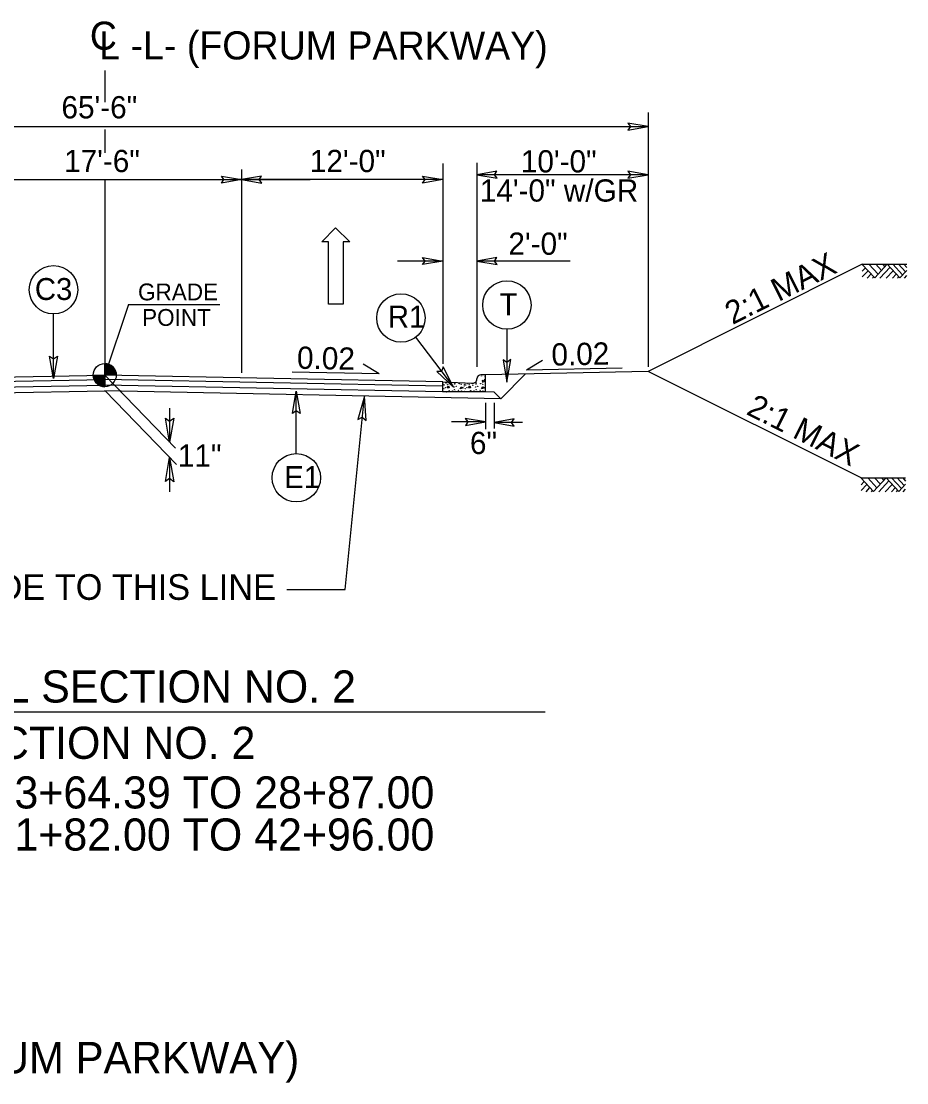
# Model space of a CAD drawing. Extents: x 1904401 to 1905163, y 193929 to 194736.
# Drawn here: x 1904906.8 to 1904958.5, y 194556.6 to 194618.6 of the extents above; entities that cross this region are included whole.
import ezdxf

# ---------------------------------------------------------------- set-up
doc = ezdxf.new("R2010")
doc.units = 0
for name, color, linetype in [('Default', 7, 'Continuous'), ('Old_Level_1', 7, 'Continuous'), ('Old_Level_11', 7, 'Continuous'), ('Old_Level_20', 7, 'Continuous'), ('Old_Level_3', 7, 'Continuous'), ('Prop Dimension Text', 7, 'Continuous'), ('Prop Lane Arrow CELL', 7, 'Continuous'), ('Typical Arrow Superelevation CELL', 7, 'Continuous'), ('Typical Berm CELL', 7, 'Continuous'), ('Typical Curb CELL', 7, 'Continuous'), ('Typical Hinge Slope Arterial CELL', 7, 'Continuous'), ('Typical Pavement Slope CELL', 7, 'Continuous'), ('Typical Terminator CELL', 7, 'Continuous'), ('Typical Text Centerline CELL', 7, 'Continuous')]:
    doc.layers.add(name, color=color, linetype=linetype)

# ---------------------------------------------------------------- blocks, each defined once
blk = doc.blocks.new('TERMINATOR')
at = {"layer": 'Typical Terminator CELL'}
blk.add_lwpolyline([(-0.469, 0.081), (0, 0), (-0.471, -0.083), (-0.411, 0)], close=True, dxfattribs=at)

msp = doc.modelspace()

# ---------------------------------------------------------------- linework, layer by layer
at = {"layer": 'Default'}
for p, q in [((1904931.41, 194610.268), (1904931.41, 194598.57)), ((1904919.66, 194609.923), (1904919.66, 194598.051))]:
    msp.add_line(p, q, dxfattribs=at)
at = {"layer": 'Old_Level_1'}
for p, q in [((1904879.91, 194612.433), (1904943.41, 194612.433)), ((1904903.66, 194609.34), (1904919.66, 194609.34)), ((1904931.41, 194609.34), (1904919.41, 194609.34)), ((1904943.41, 194609.62), (1904933.41, 194609.62)), ((1904931.41, 194604.574), (1904928.769, 194604.574)), ((1904938.856, 194604.574), (1904933.41, 194604.574)), ((1904955.93, 194604.38), (1904956.654, 194603.601)), ((1904956.321, 194604.388), (1904956.854, 194603.815)), ((1904956.654, 194603.601), (1904957.385, 194604.387)), ((1904956.719, 194604.388), (1904957.052, 194604.029)), ((1904957.121, 194604.388), (1904957.254, 194604.245)), ((1904957.385, 194604.387), (1904958.126, 194603.591)), ((1904957.707, 194604.388), (1904958.287, 194603.765)), ((1904958.04, 194604.388), (1904958.454, 194603.944)), ((1904958.36, 194604.388), (1904958.53, 194604.205)), ((1904955.93, 194603.979), (1904956.116, 194604.179)), ((1904955.93, 194603.646), (1904956.272, 194604.012)), ((1904956.218, 194603.583), (1904956.445, 194603.826)), ((1904956.964, 194603.583), (1904957.55, 194604.211)), ((1904957.334, 194603.583), (1904957.734, 194604.012)), ((1904957.7, 194603.583), (1904957.917, 194603.816)), ((1904958.126, 194603.591), (1904958.53, 194604.026)), ((1904956.529, 194603.583), (1904956.6, 194603.659)), ((1904957.995, 194603.583), (1904958.064, 194603.657)), ((1904958.396, 194603.583), (1904958.53, 194603.726)), ((1904911.66, 194597.909), (1904911.66, 194598.584)), ((1904910.985, 194597.909), (1904911.66, 194597.909)), ((1904911.658, 194597.234), (1904911.66, 194597.909)), ((1904911.66, 194597.909), (1904911.658, 194597.234)), ((1904912.335, 194597.909), (1904911.66, 194597.909)), ((1904911.66, 194597.909), (1904915.793, 194593.639)), ((1904911.678, 194596.992), (1904915.85, 194592.682)), ((1904915.454, 194595.989), (1904915.454, 194593.989)), ((1904915.449, 194593.096), (1904915.449, 194591.096)), ((1904955.862, 194591.894), (1904956.586, 194591.115)), ((1904955.862, 194591.493), (1904956.048, 194591.693)), ((1904955.862, 194591.16), (1904956.205, 194591.526)), ((1904956.151, 194591.097), (1904956.377, 194591.34)), ((1904956.254, 194591.902), (1904956.786, 194591.329)), ((1904956.586, 194591.115), (1904957.318, 194591.901)), ((1904956.652, 194591.902), (1904956.985, 194591.543)), ((1904956.896, 194591.097), (1904957.483, 194591.725)), ((1904957.053, 194591.902), (1904957.187, 194591.759)), ((1904957.267, 194591.097), (1904957.667, 194591.526)), ((1904957.318, 194591.901), (1904958.058, 194591.105)), ((1904957.639, 194591.902), (1904958.22, 194591.279)), ((1904957.972, 194591.902), (1904958.387, 194591.458)), ((1904958.058, 194591.105), (1904958.462, 194591.54)), ((1904958.293, 194591.902), (1904958.463, 194591.719)), ((1904956.461, 194591.097), (1904956.533, 194591.173)), ((1904957.633, 194591.097), (1904957.85, 194591.33)), ((1904957.927, 194591.097), (1904957.997, 194591.171)), ((1904958.328, 194591.097), (1904958.463, 194591.24)), ((1904884.997, 194578.236), (1904937.39, 194578.236))]:
    msp.add_line(p, q, dxfattribs=at)
for points in [[(1904955.93, 194604.388), (1904958.53, 194604.388)], [(1904911.666, 194598.584), (1904911.666, 194598.584), (1904911.666, 194597.909)], [(1904911.679, 194598.584), (1904911.679, 194597.909)], [(1904911.693, 194598.582), (1904911.693, 194597.909)], [(1904911.706, 194598.582), (1904911.706, 194597.909)], [(1904911.72, 194598.581), (1904911.72, 194597.909)], [(1904911.733, 194598.579), (1904911.733, 194597.909)], [(1904911.747, 194598.578), (1904911.747, 194597.909)], [(1904911.76, 194598.576), (1904911.76, 194597.909)], [(1904911.774, 194598.575), (1904911.774, 194597.909)], [(1904911.787, 194598.572), (1904911.787, 194597.909)], [(1904911.801, 194598.569), (1904911.801, 194597.909)], [(1904911.814, 194598.566), (1904911.814, 194597.909)], [(1904911.828, 194598.563), (1904911.828, 194597.909)], [(1904911.841, 194598.558), (1904911.841, 194597.909)], [(1904911.855, 194598.555), (1904911.855, 194597.909)], [(1904911.868, 194598.551), (1904911.868, 194597.909)], [(1904911.882, 194598.546), (1904911.882, 194597.909)], [(1904911.895, 194598.542), (1904911.895, 194597.909)], [(1904911.909, 194598.536), (1904911.909, 194597.909)], [(1904911.922, 194598.53), (1904911.922, 194597.909)], [(1904911.936, 194598.524), (1904911.936, 194597.909)], [(1904911.949, 194598.518), (1904911.949, 194597.909)], [(1904911.963, 194598.512), (1904911.963, 194597.909)], [(1904911.976, 194598.504), (1904911.976, 194597.909)], [(1904911.99, 194598.497), (1904911.99, 194597.909)], [(1904912.003, 194598.489), (1904912.003, 194597.909)], [(1904912.017, 194598.482), (1904912.017, 194597.909)], [(1904912.03, 194598.473), (1904912.03, 194597.909)], [(1904912.044, 194598.464), (1904912.044, 194597.909)], [(1904912.057, 194598.453), (1904912.057, 194597.909)], [(1904912.071, 194598.444), (1904912.071, 194597.909)], [(1904912.084, 194598.434), (1904912.084, 194597.909)], [(1904912.098, 194598.422), (1904912.098, 194597.909)], [(1904912.111, 194598.41), (1904912.111, 194597.909)], [(1904912.125, 194598.398), (1904912.125, 194597.909)], [(1904912.138, 194598.384), (1904912.138, 194597.909)], [(1904912.152, 194598.371), (1904912.152, 194597.909)], [(1904912.165, 194598.356), (1904912.165, 194597.909)], [(1904912.179, 194598.339), (1904912.179, 194597.909)], [(1904912.192, 194598.323), (1904912.192, 194597.909)], [(1904912.206, 194598.305), (1904912.206, 194597.909)], [(1904912.219, 194598.285), (1904912.219, 194597.909)], [(1904912.233, 194598.264), (1904912.233, 194597.909)], [(1904912.246, 194598.242), (1904912.246, 194597.909)], [(1904912.26, 194598.218), (1904912.26, 194597.909)], [(1904912.273, 194598.189), (1904912.273, 194597.909)], [(1904912.287, 194598.158), (1904912.287, 194597.909)], [(1904910.988, 194597.909), (1904910.988, 194597.835)], [(1904911.001, 194597.909), (1904911.001, 194597.756)], [(1904911.015, 194597.909), (1904911.015, 194597.708)], [(1904911.028, 194597.909), (1904911.028, 194597.667)], [(1904911.042, 194597.909), (1904911.042, 194597.636)], [(1904911.055, 194597.909), (1904911.055, 194597.607)], [(1904911.069, 194597.909), (1904911.069, 194597.582)], [(1904911.082, 194597.909), (1904911.082, 194597.558)], [(1904911.096, 194597.909), (1904911.096, 194597.537)], [(1904911.109, 194597.909), (1904911.109, 194597.517)], [(1904911.123, 194597.909), (1904911.123, 194597.499)], [(1904911.136, 194597.909), (1904911.136, 194597.483)], [(1904911.15, 194597.909), (1904911.15, 194597.466)], [(1904911.163, 194597.909), (1904911.163, 194597.451)], [(1904911.177, 194597.909), (1904911.177, 194597.436)], [(1904911.19, 194597.909), (1904911.19, 194597.423)], [(1904911.204, 194597.909), (1904911.204, 194597.411)], [(1904911.217, 194597.909), (1904911.217, 194597.399)], [(1904911.231, 194597.909), (1904911.231, 194597.387)], [(1904911.244, 194597.909), (1904911.244, 194597.376)], [(1904911.258, 194597.909), (1904911.258, 194597.366)], [(1904911.271, 194597.909), (1904911.271, 194597.357)], [(1904911.285, 194597.909), (1904911.285, 194597.348)], [(1904911.298, 194597.909), (1904911.298, 194597.339)], [(1904911.312, 194597.909), (1904911.312, 194597.33)], [(1904911.325, 194597.909), (1904911.325, 194597.322)], [(1904911.339, 194597.909), (1904911.339, 194597.315)], [(1904911.352, 194597.909), (1904911.352, 194597.307)], [(1904911.366, 194597.909), (1904911.366, 194597.301)], [(1904911.379, 194597.909), (1904911.379, 194597.295)], [(1904911.393, 194597.909), (1904911.393, 194597.289)], [(1904911.406, 194597.909), (1904911.406, 194597.283)], [(1904911.42, 194597.909), (1904911.42, 194597.277)], [(1904911.433, 194597.909), (1904911.433, 194597.273)], [(1904911.447, 194597.909), (1904911.447, 194597.268)], [(1904911.46, 194597.909), (1904911.46, 194597.264)], [(1904911.474, 194597.909), (1904911.474, 194597.261)], [(1904911.487, 194597.909), (1904911.487, 194597.256)], [(1904911.501, 194597.909), (1904911.501, 194597.253)], [(1904911.514, 194597.909), (1904911.514, 194597.25)], [(1904911.528, 194597.909), (1904911.528, 194597.247)], [(1904911.541, 194597.909), (1904911.541, 194597.244)], [(1904911.555, 194597.909), (1904911.555, 194597.243)], [(1904911.568, 194597.909), (1904911.568, 194597.24)], [(1904911.582, 194597.909), (1904911.582, 194597.238)], [(1904911.595, 194597.909), (1904911.595, 194597.237)], [(1904911.609, 194597.909), (1904911.609, 194597.235)], [(1904911.622, 194597.909), (1904911.622, 194597.235)], [(1904911.636, 194597.909), (1904911.636, 194597.234)], [(1904911.649, 194597.909), (1904911.649, 194597.234), (1904911.649, 194597.234)], [(1904912.3, 194598.12), (1904912.3, 194597.909)], [(1904912.314, 194598.074), (1904912.314, 194597.909)], [(1904912.327, 194598.005), (1904912.327, 194597.909)], [(1904955.862, 194591.902), (1904958.462, 194591.902)]]:
    msp.add_lwpolyline(points, dxfattribs=at)
msp.add_circle((1904911.659, 194597.909), 0.675, dxfattribs=at)
for start, end in [(359.99048, 89.99048), (179.99048, 269.99048)]:
    msp.add_arc((1904911.659, 194597.909), 0.675, start, end, dxfattribs=at)
at = {"layer": 'Old_Level_11'}
for p, q in [((1904908.667, 194597.706), (1904908.667, 194601.485)), ((1904929.828, 194600.123), (1904932.04, 194597.214)), ((1904935.164, 194600.592), (1904935.164, 194597.502)), ((1904922.857, 194593.327), (1904922.857, 194596.982))]:
    msp.add_line(p, q, dxfattribs=at)
for points in [[(1904908.892, 194599.015), (1904908.667, 194597.706), (1904908.434, 194599.022), (1904908.667, 194598.855)], [(1904934.939, 194598.811), (1904935.164, 194597.502), (1904935.397, 194598.818), (1904935.164, 194598.651)], [(1904931.068, 194598.12), (1904932.04, 194597.214), (1904931.429, 194598.403), (1904931.345, 194598.129)], [(1904922.632, 194595.672), (1904922.857, 194596.982), (1904923.09, 194595.665), (1904922.857, 194595.833)]]:
    msp.add_lwpolyline(points, close=True, dxfattribs=at)
for centre in [(1904908.667, 194602.899), (1904935.164, 194602.006), (1904928.972, 194601.249), (1904922.858, 194591.913)]:
    msp.add_circle(centre, 1.414, dxfattribs=at)
at = {"layer": 'Old_Level_3'}
for q in [(1904911.66, 194597.909), (1904918.393, 194602.042)]:
    msp.add_line((1904913.047, 194602.042), q, dxfattribs=at)
at = {"layer": 'Prop Dimension Text'}
for p, q in [((1904943.41, 194613.26), (1904943.41, 194598.394)), ((1904933.41, 194610.313), (1904933.41, 194598.394)), ((1904930.66, 194609.34), (1904919.66, 194609.34)), ((1904919.66, 194609.34), (1904923.66, 194609.34))]:
    msp.add_line(p, q, dxfattribs=at)
at = {"layer": 'Prop Lane Arrow CELL'}
for p, q in [((1904924.346, 194605.693), (1904925.15, 194606.51)), ((1904925.15, 194606.51), (1904925.98, 194605.693)), ((1904924.735, 194605.693), (1904924.346, 194605.693)), ((1904924.735, 194602.062), (1904924.735, 194605.693)), ((1904925.98, 194605.693), (1904925.591, 194605.693)), ((1904925.591, 194605.693), (1904925.591, 194602.062)), ((1904925.591, 194602.062), (1904924.735, 194602.062)), ((1904925.704, 194585.387), (1904926.847, 194596.688)), ((1904933.909, 194596.29), (1904933.909, 194594.751)), ((1904934.409, 194596.289), (1904934.409, 194594.791)), ((1904933.909, 194595.173), (1904931.919, 194595.173)), ((1904936.081, 194595.145), (1904934.409, 194595.145)), ((1904922.305, 194585.387), (1904925.704, 194585.387))]:
    msp.add_line(p, q, dxfattribs=at)
at = {"layer": 'Typical Arrow Superelevation CELL'}
for p, q in [((1904936.303, 194598.225), (1904937.243, 194598.793)), ((1904927.695, 194597.978), (1904926.755, 194598.546)), ((1904936.303, 194598.225), (1904941.896, 194598.337)), ((1904927.695, 194597.978), (1904922.624, 194598.08))]:
    msp.add_line(p, q, dxfattribs=at)
at = {"layer": 'Typical Berm CELL'}
msp.add_line((1904943.41, 194598.128), (1904933.909, 194597.93), dxfattribs=at)
at = {"layer": 'Typical Curb CELL'}
for p, q in [((1904933.409, 194597.68), (1904933.409, 194597.691)), ((1904933.909, 194597.93), (1904933.649, 194597.93)), ((1904933.719, 194597.597), (1904933.735, 194597.506)), ((1904933.873, 194597.552), (1904933.719, 194597.597)), ((1904933.735, 194597.506), (1904933.873, 194597.552)), ((1904933.909, 194596.931), (1904933.909, 194597.93)), ((1904931.41, 194596.931), (1904931.41, 194597.514)), ((1904931.41, 194597.514), (1904933.16, 194597.441)), ((1904933.909, 194596.931), (1904931.41, 194596.931)), ((1904931.67, 194597.17), (1904931.757, 194597.29)), ((1904931.791, 194597.176), (1904931.67, 194597.17)), ((1904931.757, 194597.29), (1904931.791, 194597.176)), ((1904932.436, 194597.119), (1904932.498, 194597.234)), ((1904932.601, 194597.159), (1904932.436, 194597.119)), ((1904932.498, 194597.234), (1904932.601, 194597.159)), ((1904932.92, 194597.17), (1904933.005, 194597.29)), ((1904933.04, 194597.176), (1904932.92, 194597.17)), ((1904933.005, 194597.29), (1904933.04, 194597.176)), ((1904933.684, 194597.119), (1904933.747, 194597.234)), ((1904933.85, 194597.159), (1904933.684, 194597.119)), ((1904933.747, 194597.234), (1904933.85, 194597.159))]:
    msp.add_line(p, q, dxfattribs=at)
for centre in [(1904933.679, 194597.855), (1904933.845, 194597.638), (1904933.896, 194597.82), (1904931.421, 194596.959), (1904931.426, 194597.268), (1904931.443, 194597.365), (1904931.483, 194597.125), (1904931.499, 194597.33), (1904931.579, 194597.17), (1904931.608, 194597.455), (1904931.631, 194596.937), (1904931.705, 194597.37), (1904931.751, 194597.472), (1904931.791, 194597.005), (1904931.899, 194597.409), (1904931.928, 194597.308), (1904931.996, 194596.982), (1904932.076, 194597.222), (1904932.105, 194597.393), (1904932.11, 194597.068), (1904932.122, 194597.444), (1904932.167, 194596.954), (1904932.202, 194597.25), (1904932.344, 194597.016), (1904932.378, 194597.415), (1904932.498, 194597.365), (1904932.515, 194596.976), (1904932.67, 194596.959), (1904932.675, 194597.268), (1904932.692, 194597.365), (1904932.732, 194597.125), (1904932.748, 194597.33), (1904932.829, 194597.17), (1904932.857, 194597.424), (1904932.88, 194596.937), (1904932.954, 194597.37), (1904933.04, 194597.005), (1904933.148, 194597.409), (1904933.177, 194597.308), (1904933.245, 194596.982), (1904933.325, 194597.222), (1904933.354, 194597.393), (1904933.359, 194597.068), (1904933.371, 194597.444), (1904933.416, 194596.954), (1904933.451, 194597.25), (1904933.593, 194597.016), (1904933.628, 194597.415), (1904933.748, 194597.365), (1904933.765, 194596.976)]:
    msp.add_circle(centre, 0.00802, dxfattribs=at)
for centre, start, end in [((1904933.17, 194597.68), 267.61554, 0), ((1904933.649, 194597.691), 90, 180)]:
    msp.add_arc(centre, 0.24, start, end, dxfattribs=at)
at = {"layer": 'Typical Hinge Slope Arterial CELL'}
for p in [(1904955.93, 194604.388), (1904955.862, 194591.902)]:
    msp.add_line(p, (1904943.41, 194598.128), dxfattribs=at)
at = {"layer": 'Typical Pavement Slope CELL'}
for p, q in [((1904891.91, 194597.514), (1904911.66, 194597.909)), ((1904891.915, 194597.264), (1904911.665, 194597.659)), ((1904931.405, 194597.264), (1904911.655, 194597.659)), ((1904931.41, 194597.514), (1904911.66, 194597.909)), ((1904934.799, 194596.531), (1904936.247, 194597.979)), ((1904888.519, 194596.529), (1904911.678, 194596.992)), ((1904891.921, 194596.931), (1904911.671, 194597.326)), ((1904934.801, 194596.529), (1904911.641, 194596.992)), ((1904931.398, 194596.931), (1904911.648, 194597.326)), ((1904934.409, 194596.921), (1904933.909, 194596.931)), ((1904934.801, 194596.529), (1904934.409, 194596.921))]:
    msp.add_line(p, q, dxfattribs=at)
at = {"layer": 'Typical Terminator CELL'}
for points in [[(1904942.238, 194612.231), (1904943.41, 194612.433), (1904942.232, 194612.641), (1904942.381, 194612.433)], [(1904918.488, 194609.542), (1904919.66, 194609.34), (1904918.482, 194609.132), (1904918.631, 194609.34)], [(1904920.831, 194609.542), (1904919.66, 194609.34), (1904920.838, 194609.132), (1904920.688, 194609.34)], [(1904930.238, 194609.542), (1904931.41, 194609.34), (1904930.232, 194609.132), (1904930.381, 194609.34)], [(1904934.581, 194609.822), (1904933.41, 194609.62), (1904934.588, 194609.412), (1904934.438, 194609.62)], [(1904942.238, 194609.418), (1904943.41, 194609.62), (1904942.232, 194609.828), (1904942.381, 194609.62)], [(1904930.238, 194604.776), (1904931.41, 194604.574), (1904930.232, 194604.366), (1904930.381, 194604.574)], [(1904934.581, 194604.776), (1904933.41, 194604.574), (1904934.588, 194604.366), (1904934.438, 194604.574)], [(1904926.934, 194595.264), (1904926.847, 194596.688), (1904926.444, 194595.31), (1904926.712, 194595.461)], [(1904932.738, 194594.971), (1904933.909, 194595.173), (1904932.731, 194595.381), (1904932.881, 194595.173)], [(1904935.581, 194595.347), (1904934.409, 194595.145), (1904935.587, 194594.937), (1904935.438, 194595.145)]]:
    msp.add_lwpolyline(points, close=True, dxfattribs=at)
at = {"layer": 'Typical Text Centerline CELL'}
for p, q in [((1904911.66, 194615.715), (1904911.66, 194613.867)), ((1904911.66, 194612.261), (1904911.66, 194610.892)), ((1904911.66, 194609.34), (1904911.66, 194597.979))]:
    msp.add_line(p, q, dxfattribs=at)

# ---------------------------------------------------------------- block references
at = {"layer": 'Old_Level_1', "xscale": 3, "yscale": 3}
for p, rotation in [((1904915.454, 194593.989), -90), ((1904915.449, 194593.096), 90)]:
    msp.add_blockref('TERMINATOR', p, dxfattribs=dict(at, rotation=rotation))

# ---------------------------------------------------------------- texts
at = {"layer": 'Old_Level_1'}
for s, height, p in [('65\'-6" ', 1.3, (1904909.132, 194612.912)), ('17\'-6" ', 1.3, (1904909.287, 194609.772)), ('12\'-0" ', 1.3, (1904923.648, 194609.772)), ('10\'-0"', 1.3, (1904935.977, 194609.753)), ('14\'-0" w/GR', 1.3, (1904933.579, 194608.049)), ('2\'-0" ', 1.3, (1904935.251, 194604.942)), ('6" ', 1.3, (1904933.003, 194593.3)), ('TYPICAL SECTION NO. 2', 1.875, (1904896.804, 194578.781))]:
    msp.add_text(s, height=height, dxfattribs=at).set_placement(p)
at = {"layer": 'Old_Level_11'}
for s, p in [('GRADE', (1904913.606, 194602.279)), ('POINT', (1904913.843, 194600.788))]:
    msp.add_text(s, height=0.984, dxfattribs=at).set_placement(p)
at = {"layer": 'Old_Level_20'}
for s, height, p in [('C3', 1.2792, (1904907.579, 194602.302)), ('T', 1.279, (1904934.735, 194601.409)), ('R1', 1.2792, (1904928.207, 194600.69)), ('11"', 1.3, (1904915.934, 194592.561)), ('E1', 1.2792, (1904922.149, 194591.316))]:
    msp.add_text(s, height=height, dxfattribs=at).set_placement(p)
at = {"layer": 'Prop Dimension Text'}
for rotation, p in [(358.8538, (1904922.886, 194598.285)), (1.1462, (1904937.778, 194598.463))]:
    msp.add_text('0.02', height=1.3, rotation=rotation, dxfattribs=at).set_placement(p)
at = {"layer": 'Prop Lane Arrow CELL'}
msp.add_text('GRADE TO THIS LINE', height=1.5, rotation=0.00016, dxfattribs=at).set_placement((1904901.05, 194584.78))
for s, p in [('USE TYPICAL SECTION NO. 2', (1904885.076, 194575.491)), ('-L- STA. 23+64.39 TO 28+87.00', (1904894.962, 194572.591)), ('-L- STA. 41+82.00 TO 42+96.00', (1904894.962, 194570.133))]:
    msp.add_text(s, height=1.875, dxfattribs=at).set_placement(p)
at = {"layer": 'Typical Hinge Slope Arterial CELL'}
for rotation, p in [(26.56505, (1904948.345, 194600.835)), (333.43495, (1904949.091, 194595.648))]:
    msp.add_text('2:1 MAX', height=1.35, rotation=rotation, dxfattribs=at).set_placement(p)
at = {"layer": 'Typical Text Centerline CELL'}
msp.add_text('C', height=1.64, dxfattribs=at).set_placement((1904910.792, 194616.923))
for s, height, rotation, p in [('L -L- (FORUM PARKWAY)', 1.64109, 359.9469, (1904911.337, 194616.363)), ('-L- (FORUM PARKWAY)', 1.83231, 0.00002, (1904895.803, 194557.115))]:
    msp.add_text(s, height=height, rotation=rotation, dxfattribs=at).set_placement(p)

doc.saveas('drawing.dxf')
